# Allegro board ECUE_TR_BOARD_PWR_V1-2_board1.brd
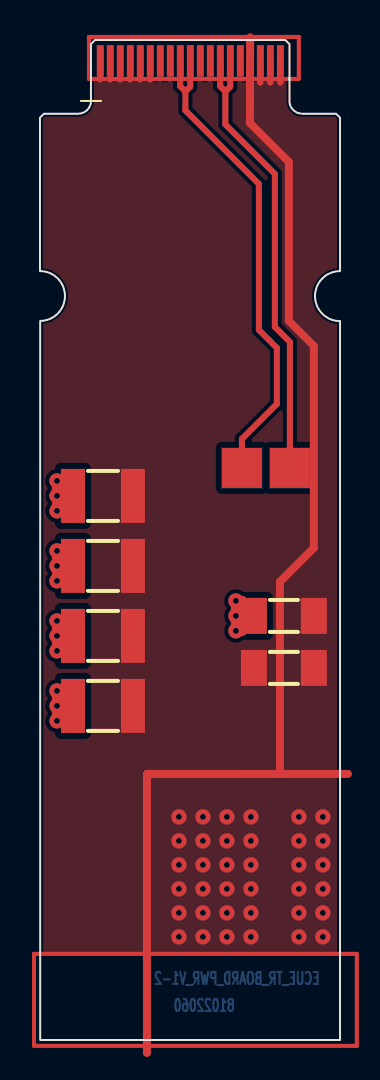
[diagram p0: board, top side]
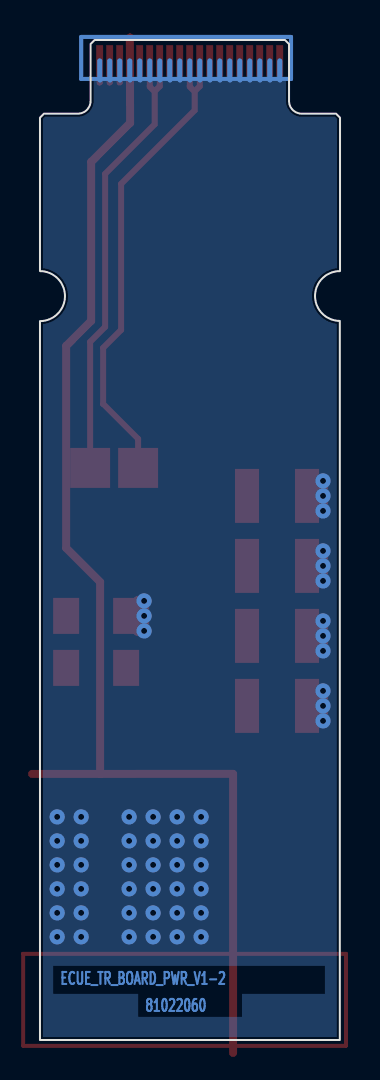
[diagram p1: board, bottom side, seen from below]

Outline 15.01 x 50.01 mm; copper layers: TOP, BOTTOM. Coordinates in mm from the lower left corner of the outline.

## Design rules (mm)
constraint set DEFAULT: min track width 0.099

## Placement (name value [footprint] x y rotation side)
C1  100uF  [C1210]  3.15 27.21 180 top
C2  100uF  [C1210]  3.15 23.71 180 top
C3  100uF  [C1210]  3.15 20.21 180 top
C4  100uF  [C1210]  3.15 16.71 180 top
C6  220uF  [C1206]  12.2 18.61 180 top
C7  220uF  [C1206]  12.2 21.21 0 top
J1  -  [ECUE_TR_BOARD_V1]  2.55 46.96 0 top
NOREF  -  []  -79.55 -42.39 0 top
NOREF#2  -  []  0.01 0 0 top
NOREF#3  -  []  0.05 0.01 90 top
NOREF#4  -  []  -2.35 37.2 90 top
NOREF#5  -  []  -12.45 39.46 90 top
NOREF#6  -  []  -12.45 39.46 0 top
TP3  -  [TP_SMD_2X2]  10.1 28.61 0 top
TP4  -  [TP_SMD_2X2]  12.5 28.61 0 top

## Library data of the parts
C1-C4 = CAPCERSMDCL2: part number: CAPCERSMDCL2_1210_GRM-100UF,6.3V; tolerance: 20%
C6 C7 = CAPCERSMDCL2: part number: CAPCERSMDCL2_1206_GRM-220UF,6.3V; tolerance: 20%
J1 = ECUE_TR_BOARD
TP3 TP4 = TP: part number: TP_SMD-2X2MM

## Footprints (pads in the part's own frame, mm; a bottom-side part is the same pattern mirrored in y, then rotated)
C1206
  rect 1.3x1.8 smd: 1(-1.5,0) 2(1.5,0)
C1210
  rect 1.2x2.7 smd: 1(-1.5,0) 2(1.5,0)
ECUE_TR_BOARD_V1
  rect 0.33x1.549 smd: A1(0.462,2.002) A2(0.963,2.002) A3(1.463,2.002) A4(1.963,2.002) A5(2.464,2.002) A6(2.964,2.002) A7(3.465,2.002) A8(3.965,2.002) A9(4.465,2.002) A10(4.966,2.002) A11(5.466,2.002) A12(5.966,2.002) A13(6.467,2.002) A14(6.967,2.002) A15(7.468,2.002) A16(7.968,2.002) A17(8.468,2.002) A18(8.969,2.002) A19(9.469,2.002) B1(0.462,2.002) B2(0.963,2.002) B3(1.463,2.002) B4(1.963,2.002) B5(2.464,2.002) B6(2.964,2.002) B7(3.465,2.002) B8(3.965,2.002) B9(4.465,2.002) B10(4.966,2.002) B11(5.466,2.002) B12(5.966,2.002) B13(6.467,2.002) B14(6.967,2.002) B15(7.468,2.002) B16(7.968,2.002) B17(8.468,2.002) B18(8.969,2.002) B19(9.469,2.002)
TP_SMD_2X2
  rect 1.999x1.999 smd: 1(0,0)

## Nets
DGND: C1.2(B<0>) C2.2(B<0>) C3.2(B<0>) C4.2(B<0>) C7.1 J1.B1 J1.B2 J1.B3 J1.B4 J1.B5 J1.B6 J1.B7 J1.B8 J1.B9 J1.B10 J1.B11 J1.B12 J1.B13 J1.B14 J1.B15 J1.B16 J1.B17 J1.B18 J1.B19
DVDD: C1.1 C2.1 C3.1 C4.1 C6.2(B<0>) J1.A1 J1.A2 J1.A3 J1.A4 J1.A5 J1.A6
PT100-N: J1.A13 J1.A14 TP4.1(A<0>)
PT100-P: J1.A9 J1.A10 TP3.1(A<0>)
VBB: C6.1 C7.2(B<0>) J1.A17 J1.A18 J1.A19

Pads without a net: J1 A7 A8 A11 A12 A15 A16

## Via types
v1: diameter 0.762, hole 0.3, TOP to BOTTOM, 51 vias

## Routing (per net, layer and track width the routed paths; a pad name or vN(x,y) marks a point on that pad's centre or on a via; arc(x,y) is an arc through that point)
DGND: length 42.5
  TOP w0.5: v1(0.85,16.71) v1(0.85,17.46) 1.15,17.46 1.65,16.96 C4.2 ; v1(0.85,16.71) C4.2 ; v1(0.85,16.71) v1(0.85,15.96) 1.15,15.96 1.65,16.46 C4.2 ; C7.1 10.7,21.06 10.1,20.46 v1(9.8,20.46) v1(9.8,21.21) ; C7.1 v1(9.8,21.21) ; C7.1 10.7,21.36 10.1,21.96 v1(9.8,21.96) v1(9.8,21.21) ; C2.2 v1(0.85,23.71) ; C2.2 1.65,23.96 1.15,24.46 v1(0.85,24.46) v1(0.85,23.71) ; C2.2 1.65,23.46 1.15,22.96 v1(0.85,22.96) v1(0.85,23.71) ; C3.2 1.65,19.96 1.15,19.46 v1(0.85,19.46) v1(0.85,20.21) ; C3.2 v1(0.85,20.21) ; C3.2 1.65,20.46 1.15,20.96 v1(0.85,20.96) v1(0.85,20.21) ; C1.2 v1(0.85,27.21) ; C1.2 1.65,26.96 1.15,26.46 v1(0.85,26.46) v1(0.85,27.21) ; C1.2 1.65,27.46 1.15,27.96 v1(0.85,27.96) v1(0.85,27.21)
  BOTTOM w0.249: 11,48.01 11.02,48.03 J1.B17 ; J1.B5 5.01,48.02 5,48.01 ; J1.B9 7.02,48.02 7,48.01 ; J1.B10 7.52,48.02 7.5,48.01 ; 8.5,48.01 8.52,48.02 J1.B12 ; J1.B11 8.02,48.02 8,48.01 ; J1.B8 6.52,48.02 6.5,48.01 ; J1.B13 9.02,48.02 9,48.01 ; J1.B4 4.51,48.02 4.5,48.01 ; J1.B2 3.51,48.02 3.5,48.01 ; 11.5,48.01 11.52,48.03 J1.B18 ; J1.B15 10.02,48.02 10,48.01 ; J1.B16 10.52,48.02 10.5,48.01 ; 12,48.01 12.02,48.03 J1.B19 ; J1.B6 5.51,48.02 5.5,48.01 ; 3,48.01 3.01,48.02 J1.B1 ; J1.B3 4.01,48.02 4,48.01 ; 6,48.01 6.01,48.02 J1.B7 ; J1.B14 9.52,48.02 9.5,48.01
  vias: v1(6.95,11.16) v1(6.95,9.96) v1(6.95,8.76) v1(6.95,7.56) v1(6.95,6.36) v1(6.95,5.16) v1(8.15,11.16) v1(8.15,9.96) v1(8.15,8.76) v1(8.15,7.56) v1(8.15,6.36) v1(8.15,5.16) v1(9.35,11.16) v1(9.35,9.96) v1(9.35,8.76) v1(9.35,7.56) v1(9.35,6.36) v1(9.35,5.16) v1(10.55,11.16) v1(10.55,9.96) v1(10.55,8.76) v1(10.55,7.56) v1(10.55,6.36) v1(10.55,5.16) v1(12.95,11.16) v1(12.95,9.96) v1(12.95,8.76) v1(12.95,7.56) v1(12.95,6.36) v1(12.95,5.16) v1(14.15,11.16) v1(14.15,9.96) v1(14.15,8.76) v1(14.15,7.56) v1(14.15,6.36) v1(14.15,5.16)
DVDD: length 5.7
  TOP w0.249: J1.A6 5.51,48.02 5.5,48.01 ; 3,48.01 3.01,48.02 J1.A1 ; 5,48.01 5.01,48.02 J1.A5 ; J1.A2 3.51,48.02 3.5,48.01 ; 4.5,48.01 4.51,48.02 J1.A4 ; J1.A3 4.01,48.02 4,48.01
PT100-N: length 23.4
  TOP w0.3: J1.A13 9.02,47.69 9.28,47.43 ; 9.28,47.43 9.52,47.67 J1.A14 ; 9.28,47.43 9.28,45.78 11.75,43.31 11.75,35.66 12.5,34.91 TP4.1
PT100-P: length 24.7
  TOP w0.3: TP3.1 10.1,30.06 11.85,31.81 11.85,34.61 10.95,35.51 10.95,42.81 7.28,46.48 7.28,47.43 ; 7.28,47.43 7.52,47.67 J1.A10 ; 7.28,47.43 7.02,47.69 J1.A9
VBB: length 3.2
  TOP w0.3: 11.03,47.88 11.02,47.89 J1.A17 ; J1.A19 12.02,47.89 12.03,47.88 ; 11.53,47.88 11.52,47.89 J1.A18

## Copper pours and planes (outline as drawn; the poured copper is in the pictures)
DGND on TOP: 5.55,4.31 5.55,13.11 11.92,13.11 12.08,13.11 14.86,13.11 14.86,4.31
DGND on BOTTOM: 0.16,0.15 0.16,35.82 1.4,37.21 0.15,38.59 0.15,46.06 0.26,46.17 1.92,46.17 2.47,46.4 2.7,46.96 2.7,48.06 12.33,48.06 12.33,46.96 12.56,46.4 13.11,46.17 14.75,46.17 14.86,46.06 14.86,38.59 13.61,37.21 14.84,35.81 14.86,35.81 14.86,0.15
DVDD on TOP: 0.16,4.31 0.16,35.82 1.4,37.21 0.15,38.59 0.15,46.06 0.26,46.17 1.92,46.17 2.47,46.4 2.7,46.96 2.7,48.06 10.31,48.06 10.3,45.77 12.25,43.82 12.25,35.87 13.5,34.62 13.5,24.69 11.8,22.99 11.8,22.82 11.8,22.82 11.8,13.51 5.15,13.51 5.15,4.31
VBB on TOP: 14.86,13.51 12.2,13.51 12.2,22.83 13.9,24.52 13.9,34.79 12.65,36.04 12.65,43.99 10.7,45.94 10.71,48.06 12.33,48.06 12.33,46.96 12.56,46.4 13.11,46.17 14.75,46.17 14.86,46.06 14.86,38.59 13.61,37.21 14.84,35.81 14.86,35.81

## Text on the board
BOTTOM: 81022060 | ECUE_TR_BOARD_PWR_V1-2
User.10: FIGURE | SIZE | 299.7 | DRILL CHART: TOP to BOTTOM | ALL UNITS ARE IN MICRONS | PLATED | QTY | 51
